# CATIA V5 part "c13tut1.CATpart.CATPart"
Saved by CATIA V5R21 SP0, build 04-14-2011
Part number: Part1
Bounding box of the stored display mesh (mm): x -49.812 to 35, y -44.222 to 44.222, z 0 to 30
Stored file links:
  D:\CATIA V5R21 E-RESOURCES\CATIA-V5R21\catia-v5r21-Tut\c13-catia-v5r21-tut\c13-catia-v5r21-tut01\c13tut01_cat_v5r21.CATPart
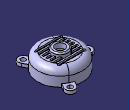
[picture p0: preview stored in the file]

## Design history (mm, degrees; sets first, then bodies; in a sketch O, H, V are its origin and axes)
Body1 (main body)
  Sketch1 on yz-plane, origin (0, 0, 0), H (0, 1, 0), V (0, 0, 1)
    line L1 (0, 0) -> (35, 0)
    line L2 (35, 0) -> (35, 15)
    arc A1 centre (25, 15) radius 10 from (35, 15) to (25, 25) ccw
    line L3 (25, 25) -> (0, 25)
    point P5 (0, 25)
    line L4 (0, 25) -> (0, 0)
    axis line L5 (0, 70.1891) -> (0, -36.6898)
    point P6 (0, 70.1891)
    "Radius" L2 L5 = 35
    distance L1 L3 = 25
    radius A1 = 10
    horizontal: L1 H
    vertical: L2 V, L4 V, L5 V
    tangency: A1 L2, L3 A1
    coincidence: P5 V, P6 V
  Shaft1: profile Sketch1, axis Sketch1.L5, angle 360
  Shell1: ExtOffset 0, Face face of Shaft1, IntOffset 2.5
  Sketch2 on face of Shaft1, origin (0, 0, 0), H (1, 0, 0), V (0, -1, 0)
    projected circle E1 centre (0, 0) radius 35 from edge [face of Shaft1 | face of Shaft1]
    projected arc E2 centre (0, 0) radius 35 from (-34.187, 7.5) to (-34.187, -7.5) ccw from edge [face of Shaft1 | face of Shaft1]
    point P1 (-34.187, 7.5)
    line L1 (-34.187, 7.5) -> (-42.5, 7.5)
    arc A1 centre (-42.5, 0) radius 7.5 from (-42.5, 7.5) to (-42.5, -7.5) ccw
    point P3 (-42.5, 0)
    line L2 (-42.5, -7.5) -> (-34.187, -7.5)
    point P5 (-34.187, -7.5)
    circle A2 centre (-42.5, 0) radius 3.75
    distance P3 V = 42.5
    radius A1 = 7.5
    radius A2 = 3.75
    coincidence: P1 E1, P5 E1, P3 H
    horizontal: L1 H, L2 H
    tangency: A1 L1, L2 A1
  Pad1: profile Sketch2, direction (0, 0, 1), length 5
  CircPattern1: of Pad1, instances 3, angular step 120 {= 360.0*1 deg/CircPattern1.AngularNumber}, axis from face of Shaft1
  Sketch3 on face of Shaft1, origin (0, 0, 25), H (1, 0, 0), V (0, 1, 0)
    construction line L1 (-20, -18) -> (20, -18)
    point P2 (20, -18)
    line L2 (-20, -16.25) -> (20, -16.25)
    line L3 (20, -19.75) -> (-20, -19.75)
    arc A1 centre (20, -18) radius 1.75 from (20, -16.25) to (20, -19.75) cw
    arc A2 centre (-20, -18) radius 1.75 from (-20, -19.75) to (-20, -16.25) cw
    length L1 = 40
    distance H L1 = 18
    distance P2 V = 20
    distance L3 L2 = 3.5
    horizontal: L1 H
    tangency: A1 L2, A2 L2, A1 L3, A2 L3
    parallelism: L1 L2
  Pocket1: profile Sketch3, direction (0, 0, -1), through (limit type 3)
  RectPattern1: of Pocket1, direction 1 instances 7, spacing 6, along yz-plane
  Sketch4 on yz-plane, origin (0, 0, 0), H (0, 1, 0), V (0, 0, 1)
    axis line L1 (0, 0) -> (0, 35.5018)
    point P2 (0, 22.5)
    line L2 (0, 22.5) -> (12.5, 22.5)
    line L3 (12.5, 22.5) -> (12.5, 28)
    arc A1 centre (10.5, 28) radius 2 from (12.5, 28) to (10.5, 30) ccw
    line L4 (10.5, 30) -> (0, 30)
    point P7 (0, 30)
    line L5 (0, 30) -> (0, 22.5)
    reference intersected line E1 (25, 22.5) -> (-25, 22.5) from face of Shell1
    "Radius" L3 L1 = 12.5
    distance L4 L2 = 7.5
    radius A1 = 2
    vertical: L1 V, L3 V, L5 V
    coincidence: P2 L1, P7 L1, L2 E1
    horizontal: L2 H, L4 H
    tangency: A1 L3, L4 A1
  Shaft2: profile Sketch4, axis Sketch4.L1, angle 360
  Sketch5 on face of Shaft2, origin (0, 0, 30), H (1, 0, 0), V (0, 1, 0)
    point P1 (0, 0)
    reference projected circle E1 centre (0, 0) radius 12.5 from edge [face of Shaft2 | face of Shaft2]
    concentricity: P1 E1
  Hole1: placed by Sketch5, at (0, 0, 30) direction (0, 0, -1), diameter 15, through (limit type 3)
